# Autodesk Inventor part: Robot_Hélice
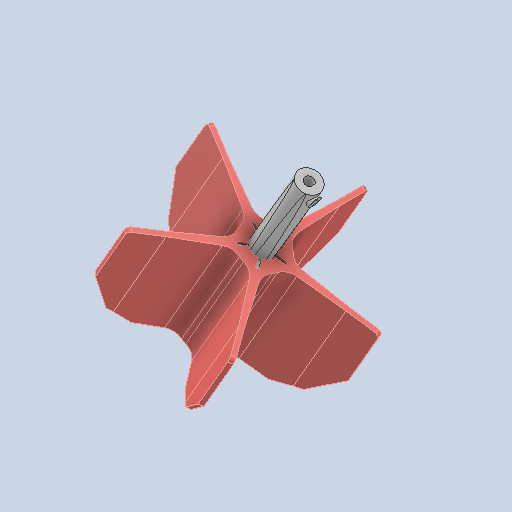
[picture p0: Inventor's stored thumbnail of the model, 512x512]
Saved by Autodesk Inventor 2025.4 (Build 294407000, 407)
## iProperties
Created: 2026-06
Part Number: Robot_Hélice
Material: Generic
Document SubType Name: Modeling
Designer: AdminForWorker
Density: 1 g/cm^3
Appearance: Default
Title: Robot_Hélice v17
Author: AdminForWorker
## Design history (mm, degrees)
feature "Hélice_frame"
feature "Hélice_flex"
body "Solid1"
body "Solid2"
